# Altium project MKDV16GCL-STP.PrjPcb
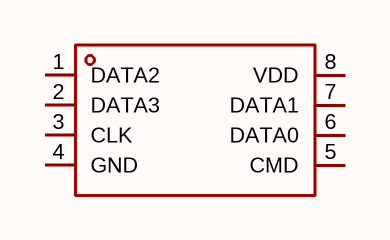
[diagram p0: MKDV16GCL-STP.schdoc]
1 sheet, 1 parts. Net scope: global (net labels, ports and power ports of the same name join across sheets).

## Sheet MKDV16GCL-STP.schdoc
size 127 x 101 mm

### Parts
U?  mkdv16gcl-stp  [LGA-8_L8.0-W6.6-P1.27-TL_MKDV16GCL-STP]  (value not drawn)

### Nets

Not connected (* = marked no-connect by the designer): U? 1(DATA2) 2(DATA3) 3(CLK) 4(GND) 5(CMD) 6(DATA0) 7(DATA1) 8(VDD)

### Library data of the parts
U? = mkdv16gcl-stp: 存储容量:16Gbit;时钟频率(fc):50MHz;工作电压:2.7V~3.6V;; Manufacturer: MK(米客方德); AddInBom: yes; ModelId: cb666697461d4e7fa3ab5c9a2ecf3791; ModelTransform: 314.96,259.842,0,0,0,0,0,0,0; Memory Size: 16Gbit; Interface: SD接口；SPI; Clock Frequency: 50MHz; Standby Supply Current: 250uA; Program / Erase Cycles: 5千次; ECC: 有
